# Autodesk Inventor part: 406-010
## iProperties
Shininess: 64.0
Length Units: 11272
Angle Units: 11279
Time Units: 11290
Mass Units: 11286
Length Display Precision: 3
Angle Display Precision: 2
Compacted: True
Part Number: 406-010
Document SubType Name: Modeling
Created: 2003-03
Designer: Charles Bliss
Material: PVC-Piping
Density: 0.0
Volumn: 0.0
Area: 0.0
PropertySet Name: Model Information
Control State: 0
Master: False
Checked Out: False
d2: 0.080 in
Author: Charles Bliss
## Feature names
1. Sweep1
2. Extrusion1
3. Extrusion2
